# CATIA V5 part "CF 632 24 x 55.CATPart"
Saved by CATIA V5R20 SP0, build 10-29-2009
Part number: CF 632 24 x 55
Definition: NONE
Nomenclature: CF 632 24 x 55
Source: Unknown
Description: CF 632 24 x 55
Bounding box of the stored display mesh (mm): x -13 to 42, y -22 to 22, z -22 to 22
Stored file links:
  C:\Users\Utente\Desktop\IO LAVORO\3D X SITO CF\X SITO\CF 632\CF 632 24 x 55.CATPart
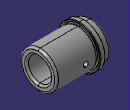
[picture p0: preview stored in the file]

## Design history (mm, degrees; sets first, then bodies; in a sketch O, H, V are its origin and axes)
Body1 "CF 632 24 x 55" (main body)
  Solid1: solid without history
